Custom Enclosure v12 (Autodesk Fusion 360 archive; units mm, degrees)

design "Custom Enclosure" references "4x AA Alkaline 1.5 V Battery Pack", "ESP32C3", "autodesk 3ax table head yxz"
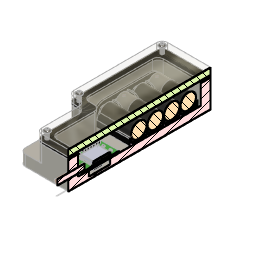
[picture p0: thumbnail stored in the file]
component_insert "Component Insert1"
component_insert "Component Insert2"
sketch "Sketch1" plane through (0, 0, 0) normal (0, 1, 0) x axis (1, 0, 0)
ground "Ground1"
position "Position1"
ground "Ground2"
sketch "Sketch1" plane through (0, 0, 0) normal (0, 1, 0) x axis (1, 0, 0)
  line L1 (0, 34.798) -> (-27.94, 34.798)
  line L2 (0, 0) -> (0, 34.798)
  line L3 (-27.94, 0) -> (0, 0)
  line L4 (-27.94, 34.798) -> (-27.94, 0)
  line L5 (15, 44.5773) -> (15, 106.9773)
  line L6 (-43, 44.5773) -> (15, 44.5773)
  line L7 (-43, 106.9773) -> (-43, 44.5773)
  line L8 (15, 106.9773) -> (-43, 106.9773)
  line L9 (13.2, 46.3773) -> (11.7, 46.3773)
  line L10 (13.2, 105.1773) -> (13.2, 46.3773)
  line L11 (11.7, 105.1773) -> (13.2, 105.1773)
  line L12 (11.7, 46.3773) -> (11.7, 105.1773)
  line L13 (10, 44.5773) -> (10, 44.798)
  line L14 (-37.94, 44.798) -> (-37.94, 44.5773)
  line L15 (25, 37.5773) -> (25, 113.9773)
  line L16 (-53, 113.9773) -> (-53, 37.5773)
  line L17 (20, 118.9773) -> (-48, 118.9773)
  line L18 (-32.94, -12) -> (5, -12)
  line L19 (-37.94, 27.5773) -> (-37.94, -7)
  line L20 (-37.94, 44.798) -> (-37.94, 44.5773)
  line L21 (15, 32.5773) -> (20, 32.5773)
  line L22 (-48, 32.5773) -> (-42.94, 32.5773)
  line L23 (10, 44.5773) -> (10, 44.798)
  line L24 (10, -7) -> (10, 27.5773)
  circle C1 centre (-24.13, 1.524) radius 0.5
  circle C2 centre (-24.13, 5.09) radius 0.5
  circle C3 centre (-24.13, 7.63) radius 0.5
  circle C4 centre (-24.13, 10.17) radius 0.5
  circle C5 centre (-24.13, 12.71) radius 0.5
  circle C6 centre (-18.542, 2.54) radius 1.1
  circle C7 centre (-15.322, 17.286) radius 0.15
  circle C8 centre (-14.772, 16.736) radius 0.15
  circle C9 centre (-14.222, 17.286) radius 0.15
  circle C10 centre (-13.672, 16.736) radius 0.15
  circle C11 centre (-13.122, 17.286) radius 0.15
  circle C12 centre (-24.13, 18.288) radius 0.5
  circle C13 centre (-24.13, 20.828) radius 0.5
  circle C14 centre (-24.13, 23.368) radius 0.5
  circle C15 centre (-24.13, 25.908) radius 0.5
  circle C16 centre (-24.13, 28.448) radius 0.5
  circle C17 centre (-24.13, 30.988) radius 0.5
  circle C18 centre (-15.322, 18.386) radius 0.15
  circle C19 centre (-14.772, 17.836) radius 0.15
  circle C20 centre (-14.222, 18.386) radius 0.15
  circle C21 centre (-14.772, 18.936) radius 0.15
  circle C22 centre (-13.672, 17.836) radius 0.15
  circle C23 centre (-13.672, 18.936) radius 0.15
  circle C24 centre (-13.122, 18.386) radius 0.15
  circle C25 centre (-1.778, 1.778) radius 1.1
  circle C26 centre (-1.778, 33.02) radius 1.1
  circle C27 centre (-14, 97.9773) radius 1.44
  circle C28 centre (-14, 53.5773) radius 1.44
  arc A1 centre (-42.94, 27.5773) radius 5 clockwise from (-42.94, 32.5773) to (-37.94, 27.5773)
  arc A2 centre (-48, 37.5773) radius 5 clockwise from (-48, 32.5773) to (-53, 37.5773)
  arc A3 centre (15, 27.5773) radius 5 clockwise from (10, 27.5773) to (15, 32.5773)
  arc A4 centre (20, 37.5773) radius 5 clockwise from (25, 37.5773) to (20, 32.5773)
  arc A5 centre (-32.94, -7) radius 5 clockwise from (-32.94, -12) to (-37.94, -7)
  arc A6 centre (5, -7) radius 5 clockwise from (10, -7) to (5, -12)
  arc A7 centre (-48, 113.9773) radius 5 clockwise from (-53, 113.9773) to (-48, 118.9773)
  arc A8 centre (20, 113.9773) radius 5 clockwise from (20, 118.9773) to (25, 113.9773)
  point P44 (-37.94, 44.5773)
  point P45 (10, 44.5773)
  parallel L2 L13
  coincident L6 P44
  coincident L6 P45
  parallel L2 L23
  parallel L3 L18
  parallel L4 L19
  collinear L19 L20
  parallel L5 L15
  parallel L6 L21
  parallel L7 L16
  parallel L8 L17
  collinear L21 L22
  collinear L23 L24
  tangent L19 A1
  tangent L22 A1
  tangent L16 A2
  tangent L22 A2
  equal A1 A2
  tangent L21 A3
  tangent L24 A3
  equal A1 A3
  tangent L15 A4
  tangent L21 A4
  equal A1 A4
  tangent L18 A5
  tangent L19 A5
  equal A1 A5
  tangent L18 A6
  tangent L24 A6
  equal A1 A6
  tangent L16 A7
  tangent L17 A7
  equal A1 A7
  tangent L15 A8
  tangent L17 A8
  equal A1 A8
  dimension "d20" radius A1 = 5
  dimension "d33" distance L8 L17 = 12
  dimension "d34" distance L6 L22 = 12
  dimension "d35" distance L3 L18 = 12
extrude "Extrude1" new body sketch "Sketch1" profile of L15 L22 L16 L17 L24 L20 L18 A1 A2 A3 A4 A5 A6 A7 A8 along normal blind 18 and against normal blind 7.4
sketch "Sketch2" plane through (0, 0, 0) normal (0, 1, 0) x axis (1, 0, 0)
  line L1 (0, 34.798) -> (-27.94, 34.798)
  line L2 (0, 0) -> (0, 34.798)
  line L3 (-27.94, 0) -> (0, 0)
  line L4 (-27.94, 34.798) -> (-27.94, 0)
  line L5 (15, 44.5773) -> (15, 106.9773)
  line L6 (-43, 44.5773) -> (15, 44.5773)
  line L7 (-43, 106.9773) -> (-43, 44.5773)
  line L8 (15, 106.9773) -> (-43, 106.9773)
  line L9 (13.2, 46.3773) -> (11.7, 46.3773)
  line L10 (13.2, 105.1773) -> (13.2, 46.3773)
  line L11 (11.7, 105.1773) -> (13.2, 105.1773)
  line L12 (11.7, 46.3773) -> (11.7, 105.1773)
  line L13 (20, 46.5773) -> (20, 104.9773)
  line L14 (-48, 104.9773) -> (-48, 46.5773)
  line L15 (15, 109.9773) -> (-43, 109.9773)
  line L16 (-27.94, -3) -> (0, -3)
  line L17 (-32.94, 36.5773) -> (-32.94, 2)
  line L18 (5, 2) -> (5, 36.5773)
  line L19 (10, 41.5773) -> (15, 41.5773)
  line L20 (-43, 41.5773) -> (-37.94, 41.5773)
  circle C1 centre (-24.13, 1.524) radius 0.5
  circle C2 centre (-24.13, 5.09) radius 0.5
  circle C3 centre (-24.13, 7.63) radius 0.5
  circle C4 centre (-24.13, 10.17) radius 0.5
  circle C5 centre (-24.13, 12.71) radius 0.5
  circle C6 centre (-18.542, 2.54) radius 1.1
  circle C7 centre (-15.322, 17.286) radius 0.15
  circle C8 centre (-14.772, 16.736) radius 0.15
  circle C9 centre (-14.222, 17.286) radius 0.15
  circle C10 centre (-13.672, 16.736) radius 0.15
  circle C11 centre (-13.122, 17.286) radius 0.15
  circle C12 centre (-24.13, 18.288) radius 0.5
  circle C13 centre (-24.13, 20.828) radius 0.5
  circle C14 centre (-24.13, 23.368) radius 0.5
  circle C15 centre (-24.13, 25.908) radius 0.5
  circle C16 centre (-24.13, 28.448) radius 0.5
  circle C17 centre (-24.13, 30.988) radius 0.5
  circle C18 centre (-15.322, 18.386) radius 0.15
  circle C19 centre (-14.772, 17.836) radius 0.15
  circle C20 centre (-14.222, 18.386) radius 0.15
  circle C21 centre (-14.772, 18.936) radius 0.15
  circle C22 centre (-13.672, 17.836) radius 0.15
  circle C23 centre (-13.672, 18.936) radius 0.15
  circle C24 centre (-13.122, 18.386) radius 0.15
  circle C25 centre (-1.778, 1.778) radius 1.1
  circle C26 centre (-1.778, 33.02) radius 1.1
  circle C27 centre (-14, 97.9773) radius 1.44
  circle C28 centre (-14, 53.5773) radius 1.44
  arc A1 centre (-43, 46.5773) radius 5 clockwise from (-43, 41.5773) to (-48, 46.5773)
  arc A2 centre (-37.94, 36.5773) radius 5 clockwise from (-37.94, 41.5773) to (-32.94, 36.5773)
  arc A3 centre (-27.94, 2) radius 5 clockwise from (-27.94, -3) to (-32.94, 2)
  arc A4 centre (0, 2) radius 5 clockwise from (5, 2) to (0, -3)
  arc A5 centre (10, 36.5773) radius 5 clockwise from (5, 36.5773) to (10, 41.5773)
  arc A6 centre (15, 46.5773) radius 5 clockwise from (20, 46.5773) to (15, 41.5773)
  arc A7 centre (-43, 104.9773) radius 5 clockwise from (-48, 104.9773) to (-43, 109.9773)
  arc A8 centre (15, 104.9773) radius 5 clockwise from (15, 109.9773) to (20, 104.9773)
  parallel L3 L16
  parallel L4 L17
  parallel L2 L18
  parallel L5 L13
  parallel L6 L19
  parallel L7 L14
  parallel L8 L15
  collinear L19 L20
  tangent L14 A1
  tangent L20 A1
  tangent L20 A2
  tangent L17 A2
  tangent L16 A3
  tangent L17 A3
  equal A2 A3
  tangent L16 A4
  tangent L18 A4
  equal A2 A4
  tangent L19 A5
  tangent L18 A5
  equal A2 A5
  tangent L13 A6
  tangent L19 A6
  equal A2 A6
  tangent L14 A7
  tangent L15 A7
  equal A2 A7
  tangent L13 A8
  tangent L15 A8
  equal A2 A8
  dimension "d23" radius A1 = 5
  dimension "d24" radius A2 = 5
  dimension "d30" distance L8 L15 = 3
  dimension "d31" distance L6 L20 = 3
  dimension "d32" distance L3 L16 = 3
extrude "Extrude4" cut sketch "Sketch2" profile of L14 L13 L20 L15 L16 L18 L17 A1 A2 A3 A4 A5 A6 A7 A8 to an object
sketch "Sketch3" plane through (0, 0, 0) normal (0, 1, 0) x axis (-1, 0, 0)
  line L1 (0, 5) -> (27.94, 5)
  line L2 (-5, -106.9773) -> (-5, 0)
  line L3 (53, -111.9773) -> (0, -111.9773)
  line L4 (37.94, -39.5773) -> (53, -39.5773)
  line L5 (32.94, 0) -> (32.94, -34.5773)
  line L6 (19.713, -21.28) -> (19.713, -12.23)
  line L7 (9.713, -12.23) -> (9.713, -21.28)
  line L8 (9.713, -16.755) -> (19.713, -16.755)
  line L9 (17.213, -5.755) -> (12.213, -5.755)
  line L10 (22.213, -22.755) -> (22.213, -10.755)
  line L11 (12.213, -27.755) -> (17.213, -27.755)
  line L12 (7.213, -10.755) -> (7.213, -22.755)
  line L13 (22.213, -27.755) -> (7.213, -5.755)
  line L14 (7.213, -27.755) -> (22.213, -5.755)
  line L15 (53, -39.5773) -> (53, -111.9773)
  line L16 (-20, -104.9773) -> (-20, -46.5773)
  line L17 (43, -109.9773) -> (-15, -109.9773)
  line L18 (48, -46.5773) -> (48, -104.9773)
  line L19 (37.94, -41.5773) -> (43, -41.5773)
  line L20 (32.94, -2) -> (32.94, -36.5773)
  line L21 (0, 3) -> (27.94, 3)
  line L22 (-5, -36.5773) -> (-5, -2)
  line L23 (-15, -41.5773) -> (-10, -41.5773)
  arc A1 centre (27.94, 0) radius 5 clockwise from (27.94, 5) to (32.94, 0)
  arc A2 centre (0, 0) radius 5 clockwise from (-5, 0) to (0, 5)
  arc A3 centre (0, -106.9773) radius 5 clockwise from (0, -111.9773) to (-5, -106.9773)
  arc A4 centre (37.94, -34.5773) radius 5 clockwise from (37.94, -39.5773) to (32.94, -34.5773)
  arc A5 centre (17.213, -22.755) radius 5 clockwise from (22.213, -22.755) to (17.213, -27.755)
  arc A6 centre (17.213, -10.755) radius 5 clockwise from (17.213, -5.755) to (22.213, -10.755)
  arc A7 centre (12.213, -10.755) radius 5 clockwise from (7.213, -10.755) to (12.213, -5.755)
  arc A8 centre (12.213, -22.755) radius 5 clockwise from (12.213, -27.755) to (7.213, -22.755)
  arc A9 centre (-15, -46.5773) radius 5 clockwise from (-20, -46.5773) to (-15, -41.5773)
  arc A10 centre (-15, -104.9773) radius 5 clockwise from (-15, -109.9773) to (-20, -104.9773)
  arc A11 centre (43, -104.9773) radius 5 clockwise from (48, -104.9773) to (43, -109.9773)
  arc A12 centre (43, -46.5773) radius 5 clockwise from (43, -41.5773) to (48, -46.5773)
  arc A13 centre (37.94, -36.5773) radius 5 clockwise from (37.94, -41.5773) to (32.94, -36.5773)
  arc A14 centre (27.94, -2) radius 5 clockwise from (27.94, 3) to (32.94, -2)
  arc A15 centre (0, -2) radius 5 clockwise from (-5, -2) to (0, 3)
  arc A16 centre (-10, -36.5773) radius 5 clockwise from (-5, -36.5773) to (-10, -41.5773)
  point P20 (19.713, -16.755)
  point P21 (9.713, -16.755)
  point P26 (14.713, -16.755)
  point P24 (22.213, -27.755)
  point P23 (22.213, -5.755)
  point P22 (7.213, -5.755)
  point P25 (7.213, -27.755)
  midpoint L6 P20
  midpoint L7 P21
  horizontal L9
  perpendicular L9 L10
  parallel L9 L11
  parallel L10 L12
  coincident L13 P26
  coincident L14 P26
  midpoint L8 P26
  coincident P24 L11
  coincident P24 L10
  tangent L11 A5
  tangent L10 A5
  coincident P23 L10
  coincident P23 L9
  tangent L10 A6
  tangent L9 A6
  equal A5 A6
  coincident P22 L12
  coincident P22 L9
  tangent L12 A7
  tangent L9 A7
  equal A5 A7
  coincident P25 L11
  coincident P25 L12
  tangent L11 A8
  tangent L12 A8
  equal A5 A8
  dimension "d13" distance P22 P23 = 15
  dimension "d14" distance P22 P25 = 22
  dimension "d17" radius A5 = 5
extrude "Extrude3" cut sketch "Sketch3" profile of L9 L10 L11 L12 A5 A6 A7 A8 against normal blind 5
sketch "Sketch4" plane through (0, -7.4, 0) normal (0, -1, 0) x axis (1, 0, 0)
  line L1 (15, -32.5773) -> (20, -32.5773)
  line L2 (10, 7) -> (10, -27.5773)
  line L3 (-32.94, 12) -> (5, 12)
  line L4 (-37.94, -27.5773) -> (-37.94, 7)
  line L5 (-48, -32.5773) -> (-42.94, -32.5773)
  line L6 (-53, -113.9773) -> (-53, -37.5773)
  line L7 (20, -118.9773) -> (-48, -118.9773)
  line L8 (25, -37.5773) -> (25, -113.9773)
  line L9 (-48, 12) -> (-32.94, 12)
  line L10 (-53, -37.5773) -> (-53, 7)
  line L11 (-32.94, -37.5773) -> (-53, -37.5773)
  line L12 (-32.94, 12) -> (-32.94, -37.5773)
  line L13 (20, 12) -> (5, 12)
  line L14 (25, -37.5773) -> (25, 7)
  line L15 (5, -37.5773) -> (25, -37.5773)
  line L16 (5, 12) -> (5, -37.5773)
  line L17 (-14, -118.9773) -> (-13.97, 12)
  arc A1 centre (20, -37.5773) radius 5 clockwise from (20, -32.5773) to (25, -37.5773)
  arc A2 centre (15, -27.5773) radius 5 clockwise from (15, -32.5773) to (10, -27.5773)
  arc A3 centre (5, 7) radius 5 clockwise from (5, 12) to (10, 7)
  arc A4 centre (-32.94, 7) radius 5 clockwise from (-37.94, 7) to (-32.94, 12)
  arc A5 centre (-42.94, -27.5773) radius 5 clockwise from (-37.94, -27.5773) to (-42.94, -32.5773)
  arc A6 centre (-48, -37.5773) radius 5 clockwise from (-53, -37.5773) to (-48, -32.5773)
  arc A7 centre (-48, -113.9773) radius 5 clockwise from (-48, -118.9773) to (-53, -113.9773)
  arc A8 centre (20, -113.9773) radius 5 clockwise from (25, -113.9773) to (20, -118.9773)
  arc A9 centre (-48, 7) radius 5 clockwise from (-53, 7) to (-48, 12)
  arc A10 centre (20, 7) radius 5 clockwise from (20, 12) to (25, 7)
  circle C1 centre (-45, -24) radius 3.05
  circle C2 centre (17.0435, -24.0142) radius 3.05
  point P18 (-53, -37.5773)
  point P27 (-53, -37.5773)
  point P11 (-32.94, 12)
  point P26 (-32.94, 12)
  point P2 (25, -37.5773)
  point P30 (25, -37.5773)
  point P9 (5, 12)
  point P29 (5, 12)
  point P39 (-13.97, 12)
  point P40 (-14, -118.9773)
  point P38 (-45, -24)
  horizontal L9
  vertical L10
  horizontal L11
  vertical L12
  coincident P18 P27
  coincident P11 P26
  horizontal L13
  vertical L14
  horizontal L15
  vertical L16
  coincident P2 P30
  coincident P9 P29
  tangent L9 A9
  tangent L10 A9
  tangent L13 A10
  tangent L14 A10
  equal A9 A10
  midpoint L3 P39
  midpoint L7 P40
  symmetric C1 L17 C2
  dimension "d27" radius A9 = 5
  dimension "d67" diameter C1 = 6.1
  dimension "d68" distance L10 P38 = 8
  dimension "d69" distance L9 P38 = 36
extrude "Extrude5" add sketch "Sketch4" profile of A1 L1 A2 L2 A3 A4 L4 A5 L5 A6 L9 L10 L13 L14 A9 A10 C1 C2 against normal blind 10
sketch "Sketch6" plane through (0, 18, 0) normal (0, 1, 0) x axis (-1, 0, 0)
  line L1 (43, -41.5773) -> (37.94, -41.5773)
  line L2 (48, -104.9773) -> (48, -46.5773)
  line L3 (-15, -109.9773) -> (43, -109.9773)
  line L4 (-20, -46.5773) -> (-20, -104.9773)
  line L5 (-10, -41.5773) -> (-15, -41.5773)
  line L6 (-5, -2) -> (-5, -36.5773)
  line L7 (27.94, 3) -> (0, 3)
  line L8 (32.94, -36.5773) -> (32.94, -2)
  line L9 (-25, -113.9773) -> (-25, -37.5773)
  line L10 (48, -118.9773) -> (-20, -118.9773)
  line L11 (53, -37.5773) -> (53, -113.9773)
  line L12 (42.94, -32.5773) -> (48, -32.5773)
  line L13 (37.94, 7) -> (37.94, -27.5773)
  line L14 (-5, 12) -> (32.94, 12)
  line L15 (-10, -27.5773) -> (-10, 7)
  line L16 (-20, -32.5773) -> (-15, -32.5773)
  line L17 (13.97, 12) -> (14, -118.9773)
  arc A1 centre (43, -46.5773) radius 5 clockwise from (43, -41.5773) to (48, -46.5773)
  arc A2 centre (43, -104.9773) radius 5 clockwise from (48, -104.9773) to (43, -109.9773)
  arc A3 centre (-15, -104.9773) radius 5 clockwise from (-15, -109.9773) to (-20, -104.9773)
  arc A4 centre (-15, -46.5773) radius 5 clockwise from (-20, -46.5773) to (-15, -41.5773)
  arc A5 centre (-10, -36.5773) radius 5 clockwise from (-5, -36.5773) to (-10, -41.5773)
  arc A6 centre (0, -2) radius 5 clockwise from (-5, -2) to (0, 3)
  arc A7 centre (27.94, -2) radius 5 clockwise from (27.94, 3) to (32.94, -2)
  arc A8 centre (37.94, -36.5773) radius 5 clockwise from (37.94, -41.5773) to (32.94, -36.5773)
  arc A9 centre (-20, -37.5773) radius 5 clockwise from (-25, -37.5773) to (-20, -32.5773)
  arc A10 centre (-20, -113.9773) radius 5 clockwise from (-20, -118.9773) to (-25, -113.9773)
  arc A11 centre (48, -113.9773) radius 5 clockwise from (53, -113.9773) to (48, -118.9773)
  arc A12 centre (48, -37.5773) radius 5 clockwise from (48, -32.5773) to (53, -37.5773)
  arc A13 centre (42.94, -27.5773) radius 5 clockwise from (42.94, -32.5773) to (37.94, -27.5773)
  arc A14 centre (32.94, 7) radius 5 clockwise from (32.94, 12) to (37.94, 7)
  arc A15 centre (-5, 7) radius 5 clockwise from (-10, 7) to (-5, 12)
  arc A16 centre (-15, -27.5773) radius 5 clockwise from (-10, -27.5773) to (-15, -32.5773)
  circle C1 centre (48, -113.9773) radius 1.45
  circle C2 centre (48, -37.5773) radius 1.45
  circle C3 centre (32.94, 7) radius 1.45
  circle C4 centre (-20.0023, -113.9929) radius 1.45
  circle C5 centre (-20.0373, -37.5929) radius 1.45
  circle C6 centre (-4.9977, 6.9913) radius 1.45
  point P53 (14, -118.9773)
  point P54 (13.97, 12)
  concentric A11 C1
  concentric A12 C2
  concentric A14 C3
  equal C2 C3
  equal C1 C2
  midpoint L10 P53
  midpoint L14 P54
  symmetric C1 L17 C4
  symmetric C2 L17 C5
  symmetric C3 L17 C6
  dimension "d40" diameter C1 = 2.9
extrude "Extrude6" cut sketch "Sketch6" profile of C1 C2 C3 C4 C5 C6 against normal blind 10
sketch "Sketch1" plane through (0, 18, 0) normal (0, 1, 0) x axis (-1, 0, 0)
  line L1 (43, -41.5773) -> (37.94, -41.5773)
  line L2 (48, -104.9773) -> (48, -46.5773)
  line L3 (-15, -109.9773) -> (43, -109.9773)
  line L4 (-20, -46.5773) -> (-20, -104.9773)
  line L5 (-10, -41.5773) -> (-15, -41.5773)
  line L6 (-5, -2) -> (-5, -36.5773)
  line L7 (27.94, 3) -> (0, 3)
  line L8 (32.94, -36.5773) -> (32.94, -2)
  line L9 (-25, -113.9773) -> (-25, -37.5773)
  line L10 (48, -118.9773) -> (-20, -118.9773)
  line L11 (53, -37.5773) -> (53, -113.9773)
  line L12 (42.94, -32.5773) -> (48, -32.5773)
  line L13 (37.94, 7) -> (37.94, -27.5773)
  line L14 (-5, 12) -> (32.94, 12)
  line L15 (-10, -27.5773) -> (-10, 7)
  line L16 (-20, -32.5773) -> (-15, -32.5773)
  arc A1 centre (43, -46.5773) radius 5 clockwise from (43, -41.5773) to (48, -46.5773)
  arc A2 centre (43, -104.9773) radius 5 clockwise from (48, -104.9773) to (43, -109.9773)
  arc A3 centre (-15, -104.9773) radius 5 clockwise from (-15, -109.9773) to (-20, -104.9773)
  arc A4 centre (-15, -46.5773) radius 5 clockwise from (-20, -46.5773) to (-15, -41.5773)
  arc A5 centre (-10, -36.5773) radius 5 clockwise from (-5, -36.5773) to (-10, -41.5773)
  arc A6 centre (0, -2) radius 5 clockwise from (-5, -2) to (0, 3)
  arc A7 centre (27.94, -2) radius 5 clockwise from (27.94, 3) to (32.94, -2)
  arc A8 centre (37.94, -36.5773) radius 5 clockwise from (37.94, -41.5773) to (32.94, -36.5773)
  arc A9 centre (-20, -37.5773) radius 5 clockwise from (-25, -37.5773) to (-20, -32.5773)
  arc A10 centre (-20, -113.9773) radius 5 clockwise from (-20, -118.9773) to (-25, -113.9773)
  arc A11 centre (48, -113.9773) radius 5 clockwise from (53, -113.9773) to (48, -118.9773)
  arc A12 centre (48, -37.5773) radius 5 clockwise from (48, -32.5773) to (53, -37.5773)
  arc A13 centre (42.94, -27.5773) radius 5 clockwise from (42.94, -32.5773) to (37.94, -27.5773)
  arc A14 centre (32.94, 7) radius 5 clockwise from (32.94, 12) to (37.94, 7)
  arc A15 centre (-5, 7) radius 5 clockwise from (-10, 7) to (-5, 12)
  arc A16 centre (-15, -27.5773) radius 5 clockwise from (-10, -27.5773) to (-15, -32.5773)
  circle C1 centre (-4.9977, 6.9913) radius 1.45
  circle C2 centre (48, -113.9773) radius 1.45
  circle C3 centre (-20.0373, -37.5929) radius 1.45
  circle C4 centre (32.94, 7) radius 1.45
  circle C5 centre (48, -37.5773) radius 1.45
  circle C6 centre (-20.0023, -113.9929) radius 1.45
  circle C7 centre (32.94, 7) radius 1.55
  circle C8 centre (-5, 7) radius 1.55
  circle C9 centre (48, -37.5773) radius 1.55
  circle C10 centre (-20.0373, -37.5929) radius 1.55
  circle C11 centre (-20.0023, -113.9929) radius 1.55
  circle C12 centre (48, -113.9773) radius 1.55
  concentric A14 C7
  concentric A15 C8
  concentric A12 C9
  concentric C3 C10
  concentric C6 C11
  concentric A11 C12
  equal C11 C12
  equal C10 C11
  equal C9 C10
  equal C7 C9
  equal C7 C8
  dimension "d90" diameter C12 = 3.1
extrude "Extrude1" new body sketch "Sketch1" profile of L1 A1 L2 A2 L3 A3 L4 A4 L5 A5 L6 A6 L7 A7 L8 A8 A9 L9 A10 L10 A11 L11 A12 L12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 along normal blind 6
base_feature "Base Feature1"
position "Position2"
as_built_joint "As-built2"
ground "Ground3"
ground "Ground4"
ground "Ground5"
joint "Assemble1" alignAngle 0 alignOffsetX 0 alignOffsetY 0 alignOffsetZ 0
copy_paste "CopyPaste1"
copy_paste "CopyPaste2"
copy_paste "CopyPaste3"
copy_paste "CopyPaste4"
copy_paste "CopyPaste5"
joint "Assemble2" alignAngle 0 alignOffsetX 0 alignOffsetY 0 alignOffsetZ 0
joint "Assemble3" alignAngle 0 alignOffsetX 0 alignOffsetY 0 alignOffsetZ 0
joint "Assemble4" alignAngle 0 alignOffsetX 0 alignOffsetY 0 alignOffsetZ 0
joint "Assemble5" alignAngle 0 alignOffsetX 0 alignOffsetY 0 alignOffsetZ 0
joint "Assemble6" alignAngle 0 alignOffsetX 0 alignOffsetY 0 alignOffsetZ 0
sketch "Sketch7" plane through (0, 0, 0) normal (0, 1, 0) x axis (-1, 0, 0)
  line L1 (7.213, -10.755) -> (7.213, -22.755)
  line L2 (17.213, -5.755) -> (12.213, -5.755)
  line L3 (22.213, -22.755) -> (22.213, -10.755)
  line L4 (12.213, -27.755) -> (17.213, -27.755)
  line L5 (-20, -104.9773) -> (-20, -46.5773)
  line L6 (43, -109.9773) -> (-15, -109.9773)
  line L7 (48, -46.5773) -> (48, -104.9773)
  line L8 (37.94, -41.5773) -> (43, -41.5773)
  line L9 (32.94, -2) -> (32.94, -36.5773)
  line L10 (0, 3) -> (27.94, 3)
  line L11 (-5, -36.5773) -> (-5, -2)
  line L12 (-15, -41.5773) -> (-10, -41.5773)
  arc A1 centre (12.213, -10.755) radius 5 clockwise from (7.213, -10.755) to (12.213, -5.755)
  arc A2 centre (17.213, -10.755) radius 5 clockwise from (17.213, -5.755) to (22.213, -10.755)
  arc A3 centre (17.213, -22.755) radius 5 clockwise from (22.213, -22.755) to (17.213, -27.755)
  arc A4 centre (12.213, -22.755) radius 5 clockwise from (12.213, -27.755) to (7.213, -22.755)
  arc A5 centre (-15, -46.5773) radius 5 clockwise from (-20, -46.5773) to (-15, -41.5773)
  arc A6 centre (-15, -104.9773) radius 5 clockwise from (-15, -109.9773) to (-20, -104.9773)
  arc A7 centre (43, -104.9773) radius 5 clockwise from (48, -104.9773) to (43, -109.9773)
  arc A8 centre (43, -46.5773) radius 5 clockwise from (43, -41.5773) to (48, -46.5773)
  arc A9 centre (37.94, -36.5773) radius 5 clockwise from (37.94, -41.5773) to (32.94, -36.5773)
  arc A10 centre (27.94, -2) radius 5 clockwise from (27.94, 3) to (32.94, -2)
  arc A11 centre (0, -2) radius 5 clockwise from (-5, -2) to (0, 3)
  arc A12 centre (-10, -36.5773) radius 5 clockwise from (-5, -36.5773) to (-10, -41.5773)
  circle C1 centre (1.778, -33.02) radius 1.1
  circle C2 centre (18.542, -2.54) radius 1.1
  circle C3 centre (1.778, -1.778) radius 1.1
  circle C4 centre (1.778, -33.02) radius 0.95
  circle C5 centre (18.542, -2.54) radius 0.95
  circle C6 centre (1.778, -1.778) radius 0.95
  concentric C1 C4
  concentric C2 C5
  concentric C3 C6
  equal C4 C6
  equal C5 C6
  dimension "d91" diameter C5 = 1.9
extrude "Extrude7" cut sketch "Sketch7" profile of C4 C5 C6 against normal blind 4
base_feature "Base Feature1"
position "Position3"
copy_paste "CopyPaste6"
copy_paste "CopyPaste7"
joint "Assemble7" alignAngle 90 alignOffsetX 0 alignOffsetY 0 alignOffsetZ 0
joint "Assemble8" alignAngle 90 alignOffsetX 0 alignOffsetY 0 alignOffsetZ 0
joint "Assemble9" alignAngle 90 alignOffsetX 0 alignOffsetY 0 alignOffsetZ 0
position "Position4"
sketch "Sketch1" plane through (0, 18, 0) normal (0, 1, 0) x axis (-1, 0, 0)
  line L1 (43, -41.5773) -> (37.94, -41.5773)
  line L2 (48, -104.9773) -> (48, -46.5773)
  line L3 (-15, -109.9773) -> (43, -109.9773)
  line L4 (-20, -46.5773) -> (-20, -104.9773)
  line L5 (-10, -41.5773) -> (-15, -41.5773)
  line L6 (-5, -2) -> (-5, -36.5773)
  line L7 (27.94, 3) -> (0, 3)
  line L8 (32.94, -36.5773) -> (32.94, -2)
  line L9 (-25, -113.9773) -> (-25, -37.5773)
  line L10 (48, -118.9773) -> (-20, -118.9773)
  line L11 (53, -37.5773) -> (53, -113.9773)
  line L12 (42.94, -32.5773) -> (48, -32.5773)
  line L13 (37.94, 7) -> (37.94, -27.5773)
  line L14 (-5, 12) -> (32.94, 12)
  line L15 (-10, -27.5773) -> (-10, 7)
  line L16 (-20, -32.5773) -> (-15, -32.5773)
  circle C1 centre (-4.9977, 6.9913) radius 1.45
  circle C2 centre (48, -113.9773) radius 1.45
  circle C3 centre (-20.0373, -37.5929) radius 1.45
  circle C4 centre (32.94, 7) radius 1.45
  circle C5 centre (48, -37.5773) radius 1.45
  circle C6 centre (-20.0023, -113.9929) radius 1.45
  arc A1 centre (43, -46.5773) radius 5 clockwise from (43, -41.5773) to (48, -46.5773)
  arc A2 centre (43, -104.9773) radius 5 clockwise from (48, -104.9773) to (43, -109.9773)
  arc A3 centre (-15, -104.9773) radius 5 clockwise from (-15, -109.9773) to (-20, -104.9773)
  arc A4 centre (-15, -46.5773) radius 5 clockwise from (-20, -46.5773) to (-15, -41.5773)
  arc A5 centre (-10, -36.5773) radius 5 clockwise from (-5, -36.5773) to (-10, -41.5773)
  arc A6 centre (0, -2) radius 5 clockwise from (-5, -2) to (0, 3)
  arc A7 centre (27.94, -2) radius 5 clockwise from (27.94, 3) to (32.94, -2)
  arc A8 centre (37.94, -36.5773) radius 5 clockwise from (37.94, -41.5773) to (32.94, -36.5773)
  arc A9 centre (-20, -37.5773) radius 5 clockwise from (-25, -37.5773) to (-20, -32.5773)
  arc A10 centre (-20, -113.9773) radius 5 clockwise from (-20, -118.9773) to (-25, -113.9773)
  arc A11 centre (48, -113.9773) radius 5 clockwise from (53, -113.9773) to (48, -118.9773)
  arc A12 centre (48, -37.5773) radius 5 clockwise from (48, -32.5773) to (53, -37.5773)
  arc A13 centre (42.94, -27.5773) radius 5 clockwise from (42.94, -32.5773) to (37.94, -27.5773)
  arc A14 centre (32.94, 7) radius 5 clockwise from (32.94, 12) to (37.94, 7)
  arc A15 centre (-5, 7) radius 5 clockwise from (-10, 7) to (-5, 12)
  arc A16 centre (-15, -27.5773) radius 5 clockwise from (-10, -27.5773) to (-15, -32.5773)
extrude "Extrude1" new body sketch "Sketch1" along normal blind 2
as_built_joint "As-built3"
joint "Assemble10" alignAngle 0 alignOffsetX 0 alignOffsetY 0 alignOffsetZ 0
sketch "Sketch8" plane through (0, 0, 3) normal (0, 0, -1) x axis (-1, 0, 0)
  line L1 (0, 18) -> (27.94, 18)
  line L2 (0, 0) -> (0, 18)
  line L3 (27.94, 0) -> (0, 0)
  line L4 (27.94, 18) -> (27.94, 0)
  line L5 (10.14, 2.4) -> (7.64, 2.4)
  line L6 (8.89, 4.9) -> (8.89, 2.4)
  circle C1 centre (8.89, 4.9) radius 2.5
  point P9 (8.89, 2.4)
  point P8 (8.89, 4.9)
  point P10 (8.89, 4.9)
  midpoint L5 P9
  perpendicular L5 L6
  coincident P8 P10
  tangent L5 C1
  dimension "d92" diameter C1 = 5
extrude "Extrude8" cut sketch "Sketch8" profile of C1 to an object
sketch "Sketch1" plane through (0, 0, 12) normal (0, 0, 1) x axis (1, 0, 0)
  line L1 (5, 18) -> (5, 2.6)
  line L2 (-32.94, 18) -> (5, 18)
  line L3 (-32.94, 2.6) -> (-32.94, 18)
  line L4 (-48, 2.6) -> (-32.94, 2.6)
  line L5 (-48, -7.4) -> (-48, 2.6)
  line L6 (20, -7.4) -> (-48, -7.4)
  line L7 (20, 2.6) -> (20, -7.4)
  line L8 (5, 2.6) -> (20, 2.6)
  circle C1 centre (-8.89, 4.9) radius 2.5
  circle C2 centre (-8.89, 4.9) radius 2.5
extrude "Extrude1" new body sketch "Sketch1" profile of C1 C2 along normal blind 10 and against normal blind 15
as_built_joint "As-built4"
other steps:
create_component "CreateComponent1"
create_component "CreateComponent2"
create_component "CreateComponent3"
create_component "CreateComponent4"
joint_origin "JointOrigin1"
joint_origin "JointOrigin2"
joint_origin "JointOrigin3"
create_component "CreateComponent5"
joint_origin "JointOrigin7"
joint_origin "JointOrigin1"
joint_origin "JointOrigin7"
joint_origin "JointOrigin8"
joint_origin "JointOrigin9"
joint_origin "JointOrigin8"
joint_origin "JointOrigin10"
joint_origin "JointOrigin9"
joint_origin "JointOrigin11"
joint_origin "JointOrigin10"
joint_origin "JointOrigin11"
joint_origin "JointOrigin12"
joint_origin "JointOrigin13"
joint_origin "JointOrigin12"
create_component "CreateComponent6"

design "ESP32C3"
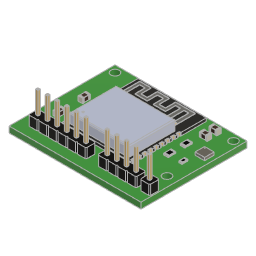
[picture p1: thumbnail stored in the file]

design "autodesk 3ax table head yxz"
named bodies: "base", "y_axis_head", "x_axis_head", "z_axis_head"

design "4x AA Alkaline 1.5 V Battery Pack"
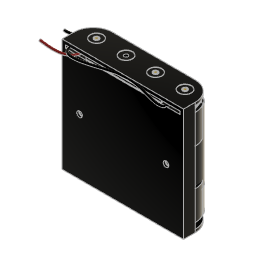
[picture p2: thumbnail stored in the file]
